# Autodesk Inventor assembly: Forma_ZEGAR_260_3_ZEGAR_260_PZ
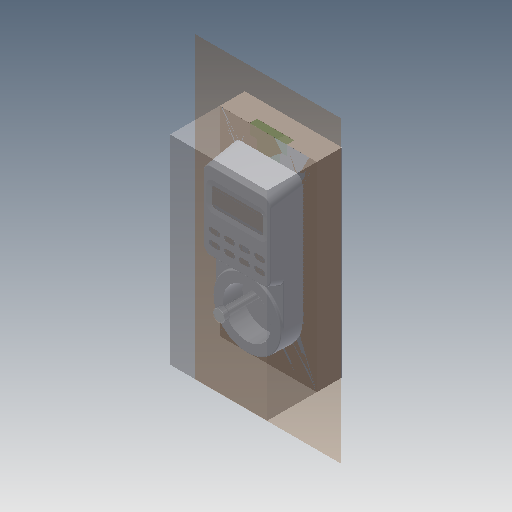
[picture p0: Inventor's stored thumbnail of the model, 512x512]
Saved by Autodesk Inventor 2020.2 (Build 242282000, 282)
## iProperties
Created: 2015-01
Part Number: Forma_ZEGAR_260_3_ZEGAR_260_PZ
Document SubType Name: Assembly
Designer: F.Stasiak
Catalog Web Link: www.expertbooks.pl
Manager: www.cadconsulting.pl
Company: Fabian Stasiak CAD Consulting
Author: F.Stasiak
Subject: Zbiór ćwiczeń. Autodesk Inventor 2020. Kurs Professional
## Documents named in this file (9)
- C:\2020_Kurs_Professional\R6 Formy\Komponenty\Forma_ZEGAR_260_3_ZEGAR_260_PZ.iam
- C:\2020_Kurs_Professional\R6 Formy\Komponenty\Forma_ZEGAR_260_3_ZEGAR_260_MP.ipt
- C:\2020_Kurs_Professional\R6 Formy\Komponenty\Forma_ZEGAR_260_3_ZEGAR_260_WP.ipt
- C:\2020_Kurs_Professional\R6 Formy\Komponenty\Forma_ZEGAR_260_3_ZEGAR_260_CR_Base.ipt
- C:\2020_Kurs_Professional\R6 Formy\Komponenty\Forma_ZEGAR_260_3_ZEGAR_260_CV_Base.ipt
- C:\2020_Kurs_Professional\R6 Formy\Komponenty\Rdzenie formujące\PUNCH_CDH\Forma_ZEGAR_260_3_ZEGAR_260_Rdzeń formujący1_Base.ipt
- C:\2020_Kurs_Professional\R6 Formy\Komponenty\Rdzenie formujące\PUNCH_CDH\Forma_ZEGAR_260_3_ZEGAR_260_Rdzeń formujący1_1.ipt
- C:\2020_Kurs_Professional\R6 Formy\Komponenty\Forma_ZEGAR_260_3_ZEGAR_260_IN1_Base.ipt
- C:\2020_Kurs_Professional\R6 Formy\Komponenty\Forma_ZEGAR_260_3_ZEGAR_260_IN1_1_1.ipt
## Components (8 placed, 8 different names)
1. Forma_ZEGAR_260_3_ZEGAR_260_MP:1 — Równoległy:1, Równoległy:2, Równoległy:3, Równoległy:4, Równoległy:5, Równoległy:6
2. Forma_ZEGAR_260_3_ZEGAR_260_WP:1 — Równoległy:4, Równoległy:5, Równoległy:6
3. Forma_ZEGAR_260_3_ZEGAR_260_CR_Base:1 — Równoległy:7, Równoległy:8, Równoległy:9
4. Forma_ZEGAR_260_3_ZEGAR_260_CV_Base:1 — Równoległy:10, Równoległy:11, Równoległy:12
5. Forma_ZEGAR_260_3_ZEGAR_260_Rdzeń formujący1_Base:1 — Kąt:1, Równoległy:20, Równoległy:21, Równoległy:22, Równoległy:32
6. Forma_ZEGAR_260_3_ZEGAR_260_Rdzeń formujący1_1:1 — Równoległy:20, Równoległy:21, Równoległy:22
7. Forma_ZEGAR_260_3_ZEGAR_260_IN1_Base:1 — Równoległy:26, Równoległy:27, Równoległy:28, Równoległy:29, Równoległy:30, Równoległy:31
8. Forma_ZEGAR_260_3_ZEGAR_260_IN1_1_1:1 — Równoległy:29, Równoległy:30, Równoległy:31
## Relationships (23: Flush 22, Angle 1)
- Równoległy:1 [Flush]: Forma_ZEGAR_260_3_ZEGAR_260_MP:1
- Równoległy:2 [Flush]: Forma_ZEGAR_260_3_ZEGAR_260_MP:1
- Równoległy:3 [Flush]: Forma_ZEGAR_260_3_ZEGAR_260_MP:1
- Równoległy:4 [Flush]: Forma_ZEGAR_260_3_ZEGAR_260_MP:1 ↔ Forma_ZEGAR_260_3_ZEGAR_260_WP:1
- Równoległy:5 [Flush]: Forma_ZEGAR_260_3_ZEGAR_260_MP:1 ↔ Forma_ZEGAR_260_3_ZEGAR_260_WP:1
- Równoległy:6 [Flush]: Forma_ZEGAR_260_3_ZEGAR_260_MP:1 ↔ Forma_ZEGAR_260_3_ZEGAR_260_WP:1
- Równoległy:7 [Flush]: Forma_ZEGAR_260_3_ZEGAR_260_CR_Base:1
- Równoległy:8 [Flush]: Forma_ZEGAR_260_3_ZEGAR_260_CR_Base:1
- Równoległy:9 [Flush]: Forma_ZEGAR_260_3_ZEGAR_260_CR_Base:1
- Równoległy:10 [Flush]: Forma_ZEGAR_260_3_ZEGAR_260_CV_Base:1
- Równoległy:11 [Flush]: Forma_ZEGAR_260_3_ZEGAR_260_CV_Base:1
- Równoległy:12 [Flush]: Forma_ZEGAR_260_3_ZEGAR_260_CV_Base:1
- Kąt:1 [Angle]: Forma_ZEGAR_260_3_ZEGAR_260_Rdzeń formujący1_Base:1
- Równoległy:20 [Flush]: Forma_ZEGAR_260_3_ZEGAR_260_Rdzeń formujący1_Base:1 ↔ Forma_ZEGAR_260_3_ZEGAR_260_Rdzeń formujący1_1:1
- Równoległy:21 [Flush]: Forma_ZEGAR_260_3_ZEGAR_260_Rdzeń formujący1_Base:1 ↔ Forma_ZEGAR_260_3_ZEGAR_260_Rdzeń formujący1_1:1
- Równoległy:22 [Flush]: Forma_ZEGAR_260_3_ZEGAR_260_Rdzeń formujący1_Base:1 ↔ Forma_ZEGAR_260_3_ZEGAR_260_Rdzeń formujący1_1:1
- Równoległy:26 [Flush]: Forma_ZEGAR_260_3_ZEGAR_260_IN1_Base:1
- Równoległy:27 [Flush]: Forma_ZEGAR_260_3_ZEGAR_260_IN1_Base:1
- Równoległy:28 [Flush]: Forma_ZEGAR_260_3_ZEGAR_260_IN1_Base:1
- Równoległy:29 [Flush]: Forma_ZEGAR_260_3_ZEGAR_260_IN1_Base:1 ↔ Forma_ZEGAR_260_3_ZEGAR_260_IN1_1_1:1
- Równoległy:30 [Flush]: Forma_ZEGAR_260_3_ZEGAR_260_IN1_Base:1 ↔ Forma_ZEGAR_260_3_ZEGAR_260_IN1_1_1:1
- Równoległy:31 [Flush]: Forma_ZEGAR_260_3_ZEGAR_260_IN1_Base:1 ↔ Forma_ZEGAR_260_3_ZEGAR_260_IN1_1_1:1
- Równoległy:32 [Flush]: Forma_ZEGAR_260_3_ZEGAR_260_Rdzeń formujący1_Base:1
